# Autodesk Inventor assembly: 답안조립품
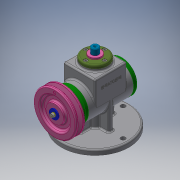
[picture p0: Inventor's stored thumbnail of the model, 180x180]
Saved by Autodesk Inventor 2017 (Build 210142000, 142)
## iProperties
Part Number: 답안조립품
Material: 일반
Document SubType Name: Assembly
Designer: 00-00
Mass: 2032.86 g
Surface Area: 1710.74 cm^2
Volume: 597.928 cm^3
Density: 3.39984 g/cm^3
Author: 00-00
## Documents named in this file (18)
- C:\Users\00-00\Documents\Inventor\600906v1003\답안조립품.iam
- C:\Users\00-00\Documents\Inventor\600906v1003\600906V1003\V-벨트풀리.ipt
- C:\Users\00-00\Documents\Inventor\600906v1003\600906V1003\가이드부시.ipt
- C:\Users\00-00\Documents\Inventor\600906v1003\600906V1003\뒤커버.ipt
- C:\Users\00-00\Documents\Inventor\600906v1003\600906V1003\멈춤링.ipt
- C:\Users\00-00\Documents\Inventor\600906v1003\600906V1003\베어링 6203.ipt
- C:\Users\00-00\Documents\Inventor\600906v1003\600906V1003\본체.ipt
- C:\Users\00-00\Documents\Inventor\600906v1003\600906V1003\볼트 M4.ipt
- C:\Users\00-00\Documents\Inventor\600906v1003\600906V1003\상부커버.ipt
- C:\Users\00-00\Documents\Inventor\600906v1003\600906V1003\스프링와셔.ipt
- C:\Users\00-00\Documents\Inventor\600906v1003\600906V1003\스프링조립용 와셔.ipt
- C:\Users\00-00\Documents\Inventor\600906v1003\600906V1003\슬라이더.ipt
- C:\Users\00-00\Documents\Inventor\600906v1003\600906V1003\앞커버.ipt
- C:\Users\00-00\Documents\Inventor\600906v1003\600906V1003\오일 실 17 30 5.ipt
- C:\Users\00-00\Documents\Inventor\600906v1003\600906V1003\키 4x4x12.ipt
- C:\Users\00-00\Documents\Inventor\600906v1003\600906V1003\편심축.ipt
- C:\Users\00-00\Documents\Inventor\600906v1003\600906V1003\평와셔.ipt
- C:\Users\00-00\Documents\Inventor\600906v1003\가변스프링.ipt
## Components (3 placed, 3 different names)
1. V-벨트풀리:1
2. 가이드부시:1
3. 가변스프링:1
